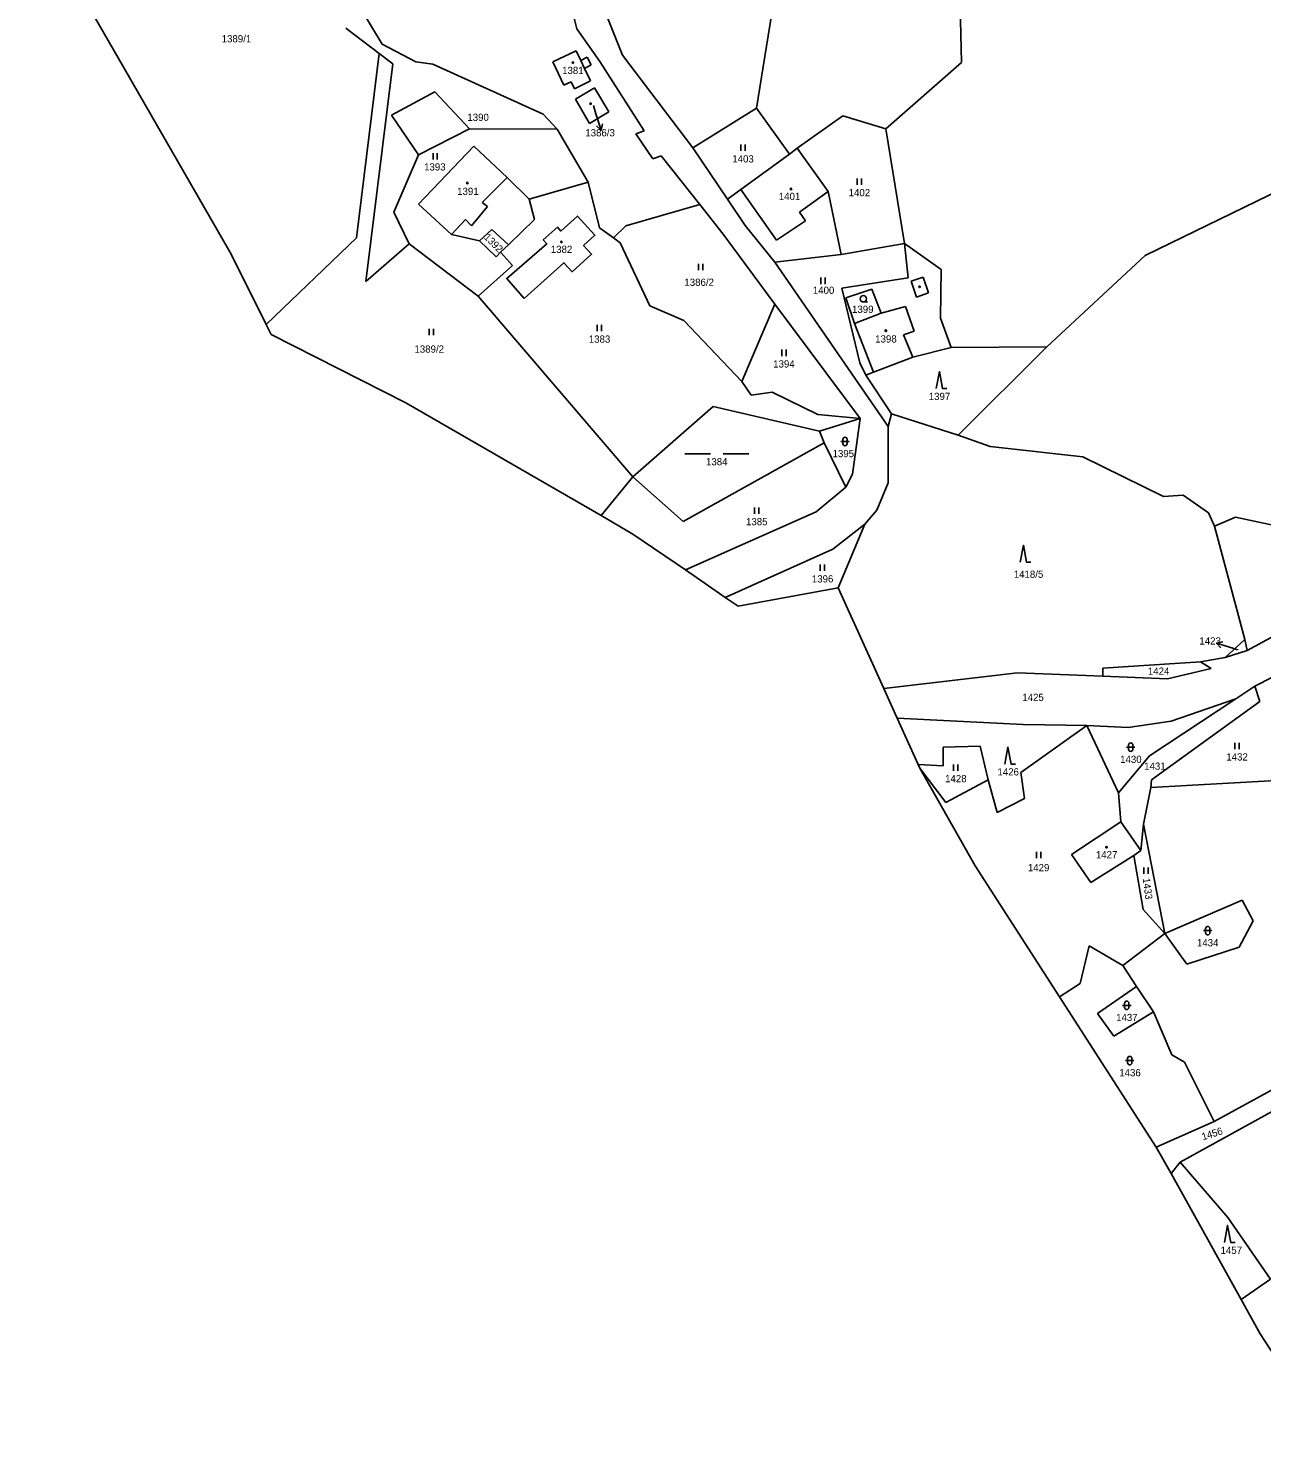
# Model space of a CAD drawing. Extents: x -670359 to -668019, y -978807 to -976674.
# Drawn here: x -669553.1 to -669263, y -978778.4 to -978442.6 of the extents above; entities that cross this region are included whole.
import ezdxf

# ---------------------------------------------------------------- set-up
doc = ezdxf.new("R2010")
doc.units = 0
for name, color, linetype in [('Hranice kat_území', 7, 'Continuous'), ('Hranice parcel', 7, 'Continuous'), ('Parcelní čísla', 7, 'Continuous'), ('Vnitřní kresba', 7, 'Continuous'), ('Značky budov', 7, 'Continuous'), ('Značky kultur', 7, 'Continuous')]:
    doc.layers.add(name, color=color, linetype=linetype)

msp = doc.modelspace()

# ---------------------------------------------------------------- linework, layer by layer
at = {"layer": 'Hranice kat_území'}
for points in [[(-669553.11, -978412.89), (-669532.01, -978449.57)], [(-669532.01, -978449.57), (-669505.47, -978495.72)], [(-669505.47, -978495.72), (-669497.18, -978512.32)], [(-669497.18, -978512.32), (-669496.01, -978514.66)], [(-669496.01, -978514.66), (-669464.32, -978530.76)], [(-669464.32, -978530.76), (-669418.43, -978557.27)], [(-669418.43, -978557.27), (-669410.93, -978561.6)], [(-669410.93, -978561.6), (-669398.56, -978570)], [(-669398.56, -978570), (-669394.19, -978573.08)], [(-669394.19, -978573.08), (-669390.55, -978575.59)], [(-669390.55, -978575.59), (-669389.2, -978576.52)], [(-669386.19, -978578.6), (-669362.66, -978574.25)], [(-669362.66, -978574.25), (-669351.92, -978597.94)], [(-669389.2, -978576.52), (-669386.19, -978578.6)], [(-669351.92, -978597.94), (-669351.29, -978599.32)], [(-669351.29, -978599.32), (-669349.86, -978602.47)], [(-669349.86, -978602.47), (-669348.75, -978604.93)], [(-669348.75, -978604.93), (-669343.8, -978615.86)], [(-669343.8, -978615.86), (-669343.44, -978616.67)], [(-669343.44, -978616.67), (-669330.41, -978639.64)], [(-669330.41, -978639.64), (-669310.53, -978670.53)], [(-669310.53, -978670.53), (-669287.79, -978705.84)], [(-669287.79, -978705.84), (-669284.31, -978712.09)], [(-669284.31, -978712.09), (-669267.86, -978741.7)], [(-669267.86, -978741.7), (-669263.36, -978749.8)], [(-669263.36, -978749.8), (-669244.69, -978778.42)]]:
    msp.add_lwpolyline(points, dxfattribs=at)
at = {"layer": 'Hranice parcel'}
for p, q in [((-669429.77, -978450.49), (-669424.25, -978447.91)), ((-669424.25, -978447.91), (-669423.18, -978450.15)), ((-669427.16, -978455.97), (-669429.77, -978450.49)), ((-669423.18, -978450.15), (-669421.65, -978449.37)), ((-669420.78, -978451.17), (-669422.29, -978452.04)), ((-669421.65, -978449.37), (-669420.78, -978451.17)), ((-669420.9, -978454.96), (-669424.66, -978456.8)), ((-669422.29, -978452.04), (-669420.9, -978454.96)), ((-669425.48, -978455.15), (-669427.16, -978455.97)), ((-669424.66, -978456.8), (-669425.48, -978455.15)), ((-669424.46, -978459.27), (-669419.95, -978456.6)), ((-669419.95, -978456.6), (-669416.55, -978462.25)), ((-669421.1, -978464.97), (-669424.46, -978459.27)), ((-669416.55, -978462.25), (-669421.1, -978464.97))]:
    msp.add_line(p, q, dxfattribs=at)
for points in [[(-669334.86, -978397.77), (-669333.58, -978450.65)], [(-669375.91, -978424.37), (-669381.83, -978461.38)], [(-669413.37, -978448.91), (-669421.55, -978428.43)], [(-669475.2, -978437.61), (-669469.93, -978446.3)], [(-669424.11, -978442.72), (-669425.28, -978437.98)], [(-669470.64, -978448.51), (-669478.46, -978442.53)], [(-669418.74, -978450.37), (-669424.11, -978442.72)], [(-669469.93, -978446.3), (-669461.97, -978450.47)], [(-669497.18, -978512.32), (-669475.98, -978491.89), (-669470.64, -978448.51)], [(-669473.72, -978502.17), (-669467.42, -978450.97)], [(-669467.42, -978450.97), (-669470.64, -978448.51)], [(-669461.97, -978450.47), (-669457.97, -978450.99)], [(-669457.97, -978450.99), (-669432, -978462.79)], [(-669408.27, -978466.72), (-669418.74, -978450.37)], [(-669396.84, -978470.74), (-669413.37, -978448.91)], [(-669333.58, -978450.65), (-669351.43, -978466.22)], [(-669381.83, -978461.38), (-669396.84, -978470.74)], [(-669381.83, -978461.38), (-669374.07, -978472.21)], [(-669432, -978462.79), (-669428.76, -978466.34)], [(-669361.56, -978463.15), (-669372.25, -978470.79)], [(-669351.43, -978466.22), (-669361.56, -978463.15)], [(-669461.4, -978472.39), (-669449.33, -978466.28)], [(-669449.33, -978466.28), (-669428.76, -978466.34)], [(-669428.76, -978466.34), (-669421.45, -978478.82)], [(-669410.2, -978467.42), (-669408.27, -978466.72)], [(-669406.26, -978473.3), (-669410.2, -978467.42)], [(-669346.99, -978493.22), (-669351.43, -978466.22)], [(-669448.33, -978470.29), (-669461.36, -978483.99)], [(-669440.49, -978477.73), (-669448.33, -978470.29)], [(-669388.68, -978482.79), (-669396.84, -978470.74)], [(-669372.25, -978470.79), (-669374.07, -978472.21)], [(-669365, -978481.03), (-669372.25, -978470.79)], [(-669237.99, -978470.53), (-669290.38, -978496.06)], [(-669467.15, -978485.84), (-669461.4, -978472.39)], [(-669404.25, -978472.6), (-669406.26, -978473.3)], [(-669395.18, -978484.09), (-669404.25, -978472.6)], [(-669374.07, -978472.21), (-669385.52, -978480.49)], [(-669435.34, -978482.83), (-669440.49, -978477.73)], [(-669435.34, -978482.83), (-669421.45, -978478.82)], [(-669421.45, -978478.82), (-669418.76, -978489.56)], [(-669385.52, -978480.49), (-669388.68, -978482.79)], [(-669361.89, -978495.81), (-669365, -978481.03)], [(-669461.36, -978483.99), (-669453.63, -978491.11)], [(-669434.11, -978487.56), (-669435.34, -978482.83)], [(-669415.49, -978491.92), (-669412.58, -978489.1), (-669395.18, -978484.09)], [(-669389.72, -978491), (-669395.18, -978484.09)], [(-669384.49, -978488.98), (-669388.68, -978482.79)], [(-669463.54, -978493.32), (-669467.15, -978485.84)], [(-669436.53, -978506.14), (-669440.59, -978501.43), (-669431.17, -978493.3), (-669432, -978492.34), (-669428.63, -978489.4), (-669427.86, -978490.31), (-669423.94, -978486.77), (-669419.85, -978491.3), (-669422.52, -978493.73), (-669420.66, -978495.77), (-669425.24, -978499.86), (-669427.14, -978497.74), (-669436.53, -978506.14)], [(-669440.17, -978493.57), (-669434.11, -978487.56)], [(-669453.63, -978491.11), (-669447.05, -978492.62)], [(-669447.05, -978492.62), (-669444.14, -978489.93)], [(-669444.14, -978489.93), (-669440.17, -978493.57)], [(-669418.76, -978489.56), (-669415.49, -978491.92)], [(-669415.49, -978491.92), (-669413.91, -978493.06)], [(-669377.56, -978507.53), (-669389.72, -978491)], [(-669377.54, -978497.61), (-669384.49, -978488.98)], [(-669463.54, -978493.32), (-669473.72, -978502.17)], [(-669447.34, -978505.65), (-669463.54, -978493.32)], [(-669447.05, -978492.62), (-669443.08, -978496.34)], [(-669443.08, -978496.34), (-669442.11, -978495.23)], [(-669442.11, -978495.23), (-669440.17, -978493.57)], [(-669439.26, -978498.38), (-669442.11, -978495.23)], [(-669413.91, -978493.06), (-669406.94, -978507.93)], [(-669346.99, -978493.22), (-669361.89, -978495.81)], [(-669338.41, -978499.31), (-669346.99, -978493.22)], [(-669346.99, -978493.22), (-669346.2, -978501.31)], [(-669447.34, -978505.65), (-669439.26, -978498.38)], [(-669361.89, -978495.81), (-669377.54, -978497.61)], [(-669350.89, -978536.26), (-669377.54, -978497.61)], [(-669290.38, -978496.06), (-669313.55, -978517.58)], [(-669346.2, -978501.31), (-669361.75, -978503.7)], [(-669338.53, -978510.83), (-669338.41, -978499.31)], [(-669361.75, -978503.7), (-669357.54, -978521.34)], [(-669360.82, -978506.03), (-669354.71, -978504.01)], [(-669354.71, -978504.01), (-669352.53, -978509.64)], [(-669410.97, -978548.12), (-669447.34, -978505.65)], [(-669406.94, -978507.93), (-669398.98, -978511.37)], [(-669385.28, -978525.68), (-669377.56, -978507.53)], [(-669357.43, -978534.38), (-669377.56, -978507.53)], [(-669358.8, -978512.05), (-669360.82, -978506.03)], [(-669398.98, -978511.37), (-669385.28, -978525.68)], [(-669352.53, -978509.64), (-669358.8, -978512.05)], [(-669336.05, -978517.73), (-669338.53, -978510.83)], [(-669336.05, -978517.73), (-669345.03, -978519.96)], [(-669313.55, -978517.58), (-669336.05, -978517.73)], [(-669334.42, -978538.31), (-669313.55, -978517.58)], [(-669357.54, -978521.34), (-669356.13, -978524.23)], [(-669345.03, -978519.96), (-669354.32, -978523.53)], [(-669354.32, -978523.53), (-669356.13, -978524.23)], [(-669356.13, -978524.23), (-669350.06, -978533.34)], [(-669383.07, -978528.9), (-669385.28, -978525.68)], [(-669378.18, -978528.24), (-669383.07, -978528.9)], [(-669367.43, -978533.47), (-669378.18, -978528.24)], [(-669410.97, -978548.12), (-669392.07, -978531.6)], [(-669392.07, -978531.6), (-669367.06, -978537.39)], [(-669357.43, -978534.38), (-669367.43, -978533.47)], [(-669367.06, -978537.39), (-669357.43, -978534.38)], [(-669359.24, -978547.5), (-669357.43, -978534.38)], [(-669350.89, -978536.26), (-669350.06, -978533.34)], [(-669350.06, -978533.34), (-669334.42, -978538.31)], [(-669367.06, -978537.39), (-669365.95, -978540.15)], [(-669350.84, -978549.57), (-669350.89, -978536.26)], [(-669334.42, -978538.31), (-669326.88, -978540.99)], [(-669399.07, -978558.64), (-669365.95, -978540.15)], [(-669365.95, -978540.15), (-669360.85, -978550.6)], [(-669326.88, -978540.99), (-669305.04, -978543.45)], [(-669305.04, -978543.45), (-669286.06, -978552.75)], [(-669418.43, -978557.27), (-669410.97, -978548.12)], [(-669410.97, -978548.12), (-669399.07, -978558.64)], [(-669360.85, -978550.6), (-669359.24, -978547.5)], [(-669367.79, -978556.4), (-669360.85, -978550.6)], [(-669353.52, -978556.01), (-669350.84, -978549.57)], [(-669286.06, -978552.75), (-669281.5, -978552.46)], [(-669281.5, -978552.46), (-669275.54, -978556.59)], [(-669398.56, -978570), (-669367.79, -978556.4)], [(-669356.36, -978559.25), (-669353.52, -978556.01)], [(-669275.54, -978556.59), (-669274.13, -978559.75)], [(-669269.15, -978557.65), (-669274.13, -978559.75)], [(-669256.69, -978560.26), (-669269.15, -978557.65)], [(-669363.86, -978565.13), (-669356.36, -978559.25)], [(-669362.66, -978574.25), (-669356.36, -978559.25)], [(-669274.13, -978559.75), (-669266.97, -978586.38)], [(-669389.2, -978576.52), (-669363.86, -978565.13)], [(-669243.09, -978576.4), (-669266.44, -978589.03)], [(-669239.98, -978584.84), (-669264.6, -978597.37)], [(-669266.97, -978586.38), (-669271.58, -978590.65)], [(-669266.44, -978589.03), (-669271.58, -978590.65)], [(-669266.97, -978586.38), (-669266.44, -978589.03)], [(-669277.35, -978591.63), (-669300.34, -978593.14)], [(-669271.58, -978590.65), (-669277.35, -978591.63)], [(-669277.35, -978591.63), (-669274.89, -978593.26)], [(-669320.44, -978594.29), (-669351.92, -978597.94)], [(-669300.36, -978595.06), (-669320.44, -978594.29)], [(-669300.34, -978593.14), (-669300.36, -978595.06)], [(-669285.16, -978595.63), (-669300.36, -978595.06)], [(-669274.89, -978593.26), (-669285.16, -978595.63)], [(-669264.6, -978597.37), (-669269.04, -978600.36)], [(-669264.6, -978597.37), (-669263.44, -978600.98)], [(-669269.04, -978600.36), (-669289.35, -978613.82)], [(-669263.44, -978600.98), (-669288.93, -978619.42)], [(-669269.04, -978600.36), (-669284.3, -978605.63)], [(-669319.13, -978606.38), (-669348.75, -978604.93)], [(-669284.3, -978605.63), (-669294.4, -978607.12)], [(-669304.16, -978606.62), (-669319.65, -978617.73)], [(-669304.16, -978606.62), (-669319.13, -978606.38)], [(-669294.4, -978607.12), (-669304.16, -978606.62)], [(-669304.16, -978606.62), (-669296.65, -978622.46)], [(-669337.92, -978611.77), (-669337.97, -978616.17)], [(-669329.19, -978611.55), (-669337.92, -978611.77)], [(-669327.35, -978619.41), (-669329.19, -978611.55)], [(-669337.97, -978616.17), (-669343.8, -978615.86)], [(-669289.35, -978613.82), (-669296.65, -978622.46)], [(-669337.34, -978624.74), (-669343.44, -978616.67)], [(-669327.35, -978619.41), (-669337.34, -978624.74)], [(-669325.19, -978627.11), (-669327.35, -978619.41)], [(-669319.65, -978617.73), (-669318.83, -978623.82)], [(-669288.93, -978619.42), (-669289.11, -978621.26)], [(-669258.19, -978619.51), (-669289.11, -978621.26)], [(-669296.65, -978622.46), (-669296.16, -978629.34)], [(-669289.11, -978621.26), (-669290.8, -978629.88)], [(-669318.83, -978623.82), (-669325.19, -978627.11)], [(-669296.16, -978629.34), (-669307.77, -978636.97)], [(-669296.16, -978629.34), (-669291.43, -978636.03)], [(-669290.8, -978629.88), (-669291.43, -978636.03)], [(-669290.8, -978629.88), (-669285.79, -978655.61)], [(-669291.43, -978636.03), (-669293.04, -978637.21)], [(-669307.77, -978636.97), (-669303.19, -978643.58)], [(-669303.19, -978643.58), (-669293.04, -978637.21)], [(-669293.04, -978637.21), (-669290.85, -978649.95)], [(-669285.79, -978655.61), (-669267.62, -978647.73)], [(-669267.62, -978647.73), (-669265.03, -978652.63)], [(-669290.85, -978649.95), (-669285.79, -978655.61)], [(-669265.03, -978652.63), (-669268.29, -978658.84)], [(-669285.79, -978655.61), (-669295.64, -978663.1)], [(-669280.58, -978662.78), (-669285.79, -978655.61)], [(-669303.59, -978658.46), (-669305.69, -978667.39)], [(-669295.64, -978663.1), (-669303.59, -978658.46)], [(-669268.29, -978658.84), (-669280.58, -978662.78)], [(-669295.64, -978663.1), (-669292.41, -978668.09)], [(-669305.69, -978667.39), (-669310.53, -978670.53)], [(-669301.6, -978674.39), (-669292.41, -978668.09)], [(-669292.41, -978668.09), (-669288.47, -978674.06)], [(-669297.81, -978679.79), (-669301.6, -978674.39)], [(-669288.47, -978674.06), (-669297.81, -978679.79)], [(-669288.47, -978674.06), (-669284.17, -978684.18)], [(-669284.17, -978684.18), (-669281.15, -978685.89)], [(-669281.15, -978685.89), (-669274.17, -978699.8)], [(-669258.23, -978691.1), (-669274.17, -978699.8)], [(-669256.11, -978695.04), (-669282.2, -978709.4)], [(-669274.17, -978699.8), (-669287.79, -978705.84)], [(-669282.2, -978709.4), (-669284.31, -978712.09)], [(-669282.2, -978709.4), (-669270.97, -978722.4)], [(-669270.97, -978722.4), (-669260.95, -978736.9)], [(-669260.95, -978736.9), (-669267.86, -978741.7)]]:
    msp.add_lwpolyline(points, dxfattribs=at)
at = {"layer": 'Parcelní čísla'}
for p, q in [((-669420.23, -978460.75), (-669419.61, -978462.74)), ((-669418.09, -978465.09), (-669418.42, -978466.56)), ((-669272.59, -978588.39), (-669273.61, -978587.29)), ((-669268.65, -978588.85), (-669269.79, -978588.49))]:
    msp.add_line(p, q, dxfattribs=at)
for points in [[(-669419.61, -978462.74), (-669418.42, -978466.56), (-669419.52, -978465.54)], [(-669269.79, -978588.49), (-669273.61, -978587.29), (-669272.14, -978586.96)]]:
    msp.add_lwpolyline(points, dxfattribs=at)
at = {"layer": 'Vnitřní kresba'}
for points in [[(-669423.18, -978450.15), (-669422.29, -978452.04)], [(-669467.71, -978463.04), (-669457.56, -978457.55)], [(-669457.56, -978457.55), (-669449.33, -978466.28)], [(-669461.4, -978472.39), (-669467.71, -978463.04)], [(-669440.49, -978477.73), (-669446.39, -978483.59)], [(-669385.52, -978480.49), (-669377.12, -978492.41)], [(-669371.73, -978485.87), (-669365, -978481.03)], [(-669445.12, -978484.56), (-669448.93, -978489.08)], [(-669446.39, -978483.59), (-669445.12, -978484.56)], [(-669450.28, -978487.62), (-669453.63, -978491.11)], [(-669448.93, -978489.08), (-669450.28, -978487.62)], [(-669377.12, -978492.41), (-669370.31, -978487.93)], [(-669370.31, -978487.93), (-669371.73, -978485.87)], [(-669345.49, -978502.13), (-669342.6, -978501.16)], [(-669342.6, -978501.16), (-669341.35, -978504.86)], [(-669344.24, -978505.83), (-669345.49, -978502.13)], [(-669341.35, -978504.86), (-669344.24, -978505.83)], [(-669352.53, -978509.64), (-669346.83, -978508.02)], [(-669346.83, -978508.02), (-669344.73, -978513.88)], [(-669354.32, -978523.53), (-669358.8, -978512.05)], [(-669344.73, -978513.88), (-669347.3, -978514.73)], [(-669347.3, -978514.73), (-669345.03, -978519.96)]]:
    msp.add_lwpolyline(points, dxfattribs=at)
at = {"layer": 'Značky budov'}
for centre in [(-669425.05, -978450.65), (-669420.89, -978460.34), (-669449.88, -978478.99), (-669373.74, -978480.4), (-669427.74, -978492.85), (-669351.42, -978513.74), (-669299.5, -978635.3)]:
    msp.add_circle(centre, 0.175, dxfattribs=at)
at = {"layer": 'Značky kultur'}
for p, q in [((-669385.54, -978469.96), (-669385.54, -978471.46)), ((-669384.54, -978471.46), (-669384.54, -978469.96)), ((-669457.95, -978471.94), (-669457.95, -978473.44)), ((-669456.95, -978473.44), (-669456.95, -978471.94)), ((-669358.17, -978477.9), (-669358.17, -978479.4)), ((-669357.17, -978479.4), (-669357.17, -978477.9)), ((-669395.48, -978497.98), (-669395.48, -978499.48)), ((-669394.48, -978499.48), (-669394.48, -978497.98)), ((-669366.72, -978501.26), (-669366.72, -978502.76)), ((-669365.72, -978502.76), (-669365.72, -978501.26)), ((-669356.71, -978506.99), (-669355.71, -978506.99)), ((-669458.82, -978513.27), (-669458.82, -978514.77)), ((-669457.82, -978514.77), (-669457.82, -978513.27)), ((-669419.3, -978512.37), (-669419.3, -978513.87)), ((-669418.3, -978513.87), (-669418.3, -978512.37)), ((-669375.88, -978518.21), (-669375.88, -978519.71)), ((-669374.88, -978519.71), (-669374.88, -978518.21)), ((-669362.02, -978539.81), (-669360.02, -978539.81)), ((-669361.52, -978539.31), (-669361.52, -978540.31)), ((-669360.52, -978539.31), (-669360.52, -978540.31)), ((-669398.69, -978542.72), (-669392.69, -978542.72)), ((-669389.69, -978542.72), (-669383.69, -978542.72)), ((-669382.31, -978555.33), (-669382.31, -978556.83)), ((-669381.31, -978556.83), (-669381.31, -978555.33)), ((-669366.86, -978568.79), (-669366.86, -978570.29)), ((-669365.86, -978570.29), (-669365.86, -978568.79)), ((-669294.8, -978611.76), (-669292.8, -978611.76)), ((-669294.3, -978611.26), (-669294.3, -978612.26)), ((-669293.3, -978611.26), (-669293.3, -978612.26)), ((-669269.32, -978610.69), (-669269.32, -978612.19)), ((-669268.32, -978612.19), (-669268.32, -978610.69)), ((-669335.48, -978615.79), (-669335.48, -978617.29)), ((-669334.48, -978617.29), (-669334.48, -978615.79)), ((-669315.94, -978636.38), (-669315.94, -978637.88)), ((-669314.94, -978637.88), (-669314.94, -978636.38)), ((-669290.69, -978640.04), (-669290.69, -978641.54)), ((-669289.69, -978641.54), (-669289.69, -978640.04)), ((-669276.69, -978654.92), (-669274.69, -978654.92)), ((-669276.19, -978654.42), (-669276.19, -978655.42)), ((-669275.19, -978654.42), (-669275.19, -978655.42)), ((-669295.74, -978672.5), (-669293.74, -978672.5)), ((-669295.24, -978672), (-669295.24, -978673)), ((-669294.24, -978672), (-669294.24, -978673)), ((-669295.04, -978685.5), (-669293.04, -978685.5)), ((-669294.54, -978685), (-669294.54, -978686)), ((-669293.54, -978685), (-669293.54, -978686))]:
    msp.add_line(p, q, dxfattribs=at)
for points in [[(-669339.57, -978527.36), (-669338.82, -978523.36), (-669338.07, -978527.36), (-669337.07, -978527.36)], [(-669319.81, -978568.24), (-669319.06, -978564.24), (-669318.31, -978568.24), (-669317.31, -978568.24)], [(-669323.45, -978615.71), (-669322.7, -978611.71), (-669321.95, -978615.71), (-669320.95, -978615.71)], [(-669271.77, -978728.29), (-669271.02, -978724.29), (-669270.27, -978728.29), (-669269.27, -978728.29)]]:
    msp.add_lwpolyline(points, dxfattribs=at)
for centre, radius in [((-669425.05, -978450.65), 0.175), ((-669420.89, -978460.34), 0.175), ((-669449.88, -978478.99), 0.175), ((-669373.74, -978480.4), 0.175), ((-669427.74, -978492.85), 0.175), ((-669343.48, -978503.41), 0.175), ((-669356.71, -978506.24), 0.75), ((-669351.42, -978513.74), 0.175), ((-669299.5, -978635.3), 0.175)]:
    msp.add_circle(centre, radius, dxfattribs=at)
for centre, start, end in [((-669361.02, -978539.31), 0, 180), ((-669361.02, -978540.31), 180, 0), ((-669293.8, -978611.26), 0, 180), ((-669293.8, -978612.26), 180, 0), ((-669275.69, -978654.42), 0, 180), ((-669275.69, -978655.42), 180, 0), ((-669294.74, -978672), 0, 180), ((-669294.74, -978673), 180, 0), ((-669294.04, -978685), 0, 180), ((-669294.04, -978686), 180, 0)]:
    msp.add_arc(centre, 0.5, start, end, dxfattribs=at)

# ---------------------------------------------------------------- texts
at = {"layer": 'Parcelní čísla'}
for s, height, p in [('1389/1', 1.7, (-669507.67, -978445.9)), ('1381', 1.7, (-669427.58, -978453.35)), ('1386/3', 0.1, (-669420.23, -978460.75)), ('1390', 1.7, (-669449.87, -978464.39)), ('1386/3', 1.7, (-669422.12, -978468.02)), ('1393', 1.7, (-669460.05, -978476.05)), ('1403', 1.7, (-669387.54, -978474.16)), ('1391', 1.7, (-669452.27, -978481.8)), ('1401', 1.7, (-669376.6, -978482.99)), ('1402', 1.7, (-669360.17, -978482.1)), ('1382', 1.7, (-669430.24, -978495.45)), ('1386/2', 1.7, (-669398.81, -978503.19)), ('1400', 1.7, (-669368.59, -978505.07)), ('1399', 1.7, (-669359.37, -978509.56)), ('1383', 1.7, (-669421.3, -978516.57)), ('1398', 1.7, (-669353.92, -978516.53)), ('1389/2', 1.7, (-669462.32, -978518.92)), ('1394', 1.7, (-669377.92, -978522.41)), ('1397', 1.7, (-669341.32, -978530.06)), ('1395', 1.7, (-669363.95, -978543.51)), ('1384', 1.7, (-669393.73, -978545.42)), ('1385', 1.7, (-669384.31, -978559.53)), ('1396', 1.7, (-669368.82, -978572.99)), ('1418/5', 1.7, (-669321.32, -978571.9)), ('1423', 1.7, (-669277.65, -978587.59)), ('1423', 0.1, (-669268.65, -978588.85)), ('1424', 1.7, (-669289.77, -978594.71)), ('1430', 1.7, (-669296.3, -978615.46)), ('1431', 1.7, (-669290.65, -978617.06)), ('1432', 1.7, (-669271.32, -978614.89)), ('1428', 1.7, (-669337.48, -978619.99)), ('1426', 1.7, (-669325.16, -978618.41)), ('1427', 1.7, (-669302, -978637.9)), ('1429', 1.7, (-669318, -978640.95)), ('1434', 1.7, (-669278.23, -978658.62)), ('1437', 1.7, (-669297.24, -978676.2)), ('1436', 1.7, (-669296.5, -978689.2)), ('1457', 1.7, (-669272.67, -978730.99))]:
    msp.add_text(s, height=height, dxfattribs=at).set_placement(p)
for s, rotation, p in [('1392', 315, (-669446.09, -978491.91)), ('1425', 0.2413, (-669319.31, -978600.89)), ('1433', 277.7836, (-669290.99, -978642.66)), ('1456', 17.3005, (-669276.82, -978704.28))]:
    msp.add_text(s, height=1.7, rotation=rotation, dxfattribs=at).set_placement(p)

doc.saveas('drawing.dxf')
